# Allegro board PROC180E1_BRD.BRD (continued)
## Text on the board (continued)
PAGE_OUTLINE: LAYOUT BY | REVIEWED BY | APPROVED BY | SIGNATURES | AMB | BR | ZA | 290424 | DATE | SCALE: | SIZE | D | NONE | TEXAS INSTRUMENTS | AM62D EVM  BOARD | SHEET 1 OF 15 | PROC180 | Rev | E1
DISPLAY_TOP: 16. | 17. | 1. | 11. | 12. | 13. | 14. | 15. | 8. | 10 | 2. | 3. | 4. | 6. | 7. | 5. | 9. | IMPEDANCE MISTRAL SHALL APPROVE THE MODIFIED WIDTHS AND SPACING. | FABRICATE PCB IN ACCORDANCE WITH IPC-6012D, CLASS 2; PER IPC-6011.  PCB SHALL BE MANUFACTURED USING  ITEQ IT 180A OR EQUIVALENT | TRACE WIDTH SHALL BE MEASURED ON THE SURFACE IN CONTACT WITH THE LAMINATE. | TEST REQUIREMENTS: | THIEVING IS ALLOWED ONLY IN THE PANEL FRAME, NOT IN THE CIRCUIT AREA. | TEAR DROPS SHALL BE ADDED ON VIA'S AND THROUGH HOLE PADS IN ALL INTERNAL AND OUTER LAYERS. | ENSURE UL REGISTERED E-FILE NUMBER SHALL BE PRINTED ON THE PCB SILKSCREEN. | VIA ON PAD SHALL BE RESIN FILLED AND CAP-PLATED. | ALL HOLES SHALL BE LOCATED WITHIN 0.15MM  DIAMETER OF TRUE POSITION. | LAYER TO LAYER REGISTRATION SHALL BE WITHIN 0.125MM. | CONDUCTOR WIDTH SHALL NOT BE LESS THAN 20% FROM ITS ORIGINAL DATA. INCASE FOR MATCHING | BOARD FINISHED SHALL BE ACCORDING TO IPC-6012D CLASS 2. | AUTOMATED OPTICAL INSPECTION OF ALL THE LAYERS IS REQUIRED. | FINISH: | ALL UNCONNECTED VIA'S SHALL BE SUPPRESSED IF REQUIRED. | FINISHED PCB THICKNESS SHALL BE 0.0427" +/-10%. | MATERIALS: | BOW AND TWIST SHALL NOT EXCEED MORE THAN 0.75% OF THE DESIGN LENGTH. | MARKING: | MIN TRACE WIDTH/SPACING ON BOARD IS 0.003"/0.00339". | IF THE SILK SCREEN FALLS ON SOLDERABLE AREAS. | THICKNESS SHALL BE 0.04-0.06 MICRONS OF SOLDERABLE IMMERSION GOLD SURFACE. | 100% NET LIST ELECTRICAL VERIFICATION USING MISTRAL SUPPLIED IPC-D-356 NET LIST FOR OPENS AND SHORTS. | LAMINATE AND PREPREG (B-STAGE) TO BE IN ACCORDANCE WITH IPC-4101/126. | (MIN.TG 170) | THAT ARE 0.08(0.003") PER SIDE SHALL BE REDUCED IF REQUIRED. | SURFACE AND VIA HOLES FINISH SHALL NOT BE LESS THAN 20UM [0.00079"], INCASE OF LASER | ALL HOLES SURROUNDED BY LAND <=0.010" SHALL BE COMPLIANCE TO IPC6012, CLASS 2. | COPPER FOIL TO BE IN ACCORDANCE WITH IPC-MF-150. UNLESS OTHERWISE SPECIFIED, | ALL EXPOSED CONDUCTIVE PATTERN AREAS NOT COVERED WITH SOLDER MASK OR OTHER PLATING SHALL BE ENIG, | ELECTROLESS NICKEL/IMMERSION GOLD, ELECTROLESS NICKEL SHALL BE 3-6 MICRONS, TYPICAL IMMERSION GOLD | APPLY LIQUID PHOTO IMAGEABLE SOLDER MASK PER IPC-SM-840, CLASS H, TO BOTH SIDES OF THE BOARD OVER BARE COPPER. | VIA HOLES SHALL BE RESIN FILLED AND COVERED WITH SOLDER MASK. ONLY SOLDER MASK IMAGES | ALL OTHER SOLDER MASK IMAGES SHALL NOT BE ENLARGED. DEFAULT COLOUR OF SOLDER MASK SHALL BE GREEN. | SILKSCREEN SHALL BE WHITE, PERMANENT, ORGANIC, NON-CONDUCTIVE INK. THERE SHALL BE | VIA'S, BLIND VIA'S SHALL NOT BE LESS THAN 12UM [0.00047"] AND BURIED VIA'S SHALL NOT BE LESS THAN 15UM [0.0006"]. | BOARD SHALL MEET THE REQUIREMENTS OF UL-796E WITH FLAMMABILITY RATING OF MINIMUM 94V-0. UL LOGO, | NO SILKSCREEN ON ANY SOLDERABLE COMPONENT PAD. CLIPPING OF SILK SCREEN SHALL BE ALLOWED | MANUFACTURER'S IDENTIFICATION AND DATE CODE LETTER SHALL BE RENDERED IN SILKSCREEN. | THE COPPER FOIL THICKNESS TOLERANCES SHALL BE AS PER IPC 6012B TABLE NO.3-7 AND 3-8. | FABRICATION NOTES:
DIMENSION: P/N AM62A LPDDR4 FAB REV 1 | LAYER 1
User.5: AM62A LPDDR4 FAB REV 1 | P/N AM62A LPDDR4 FAB REV 1 | LAYER 12
User.7: C26 | R33 | R15 | R13 | R16 | R14 | R32 | R29 | R26 | R23 | R20 | C25 | C24 | R19 | C17 | R17 | C22 | C23 | R18 | R2 | R4 | R1 | R3 | H3 | H4 | R31 | J40 | R30 | R28 | R27 | R25 | R24 | R22 | R21 | 8
User.10: SECONDARY-SIDE-SIG | 15 | PROC180E1 ASSEMBLY BOTTOM
User.11: CARD PUSH OUT | CARD PUSH LOCK | CARD PUSH IN | PROC180E1 ASSEMBLY TOP
User.12: ASSEMBLY_BOTTOM | BOTTOM ASSEMBLY OF PROC167A
User.13: 2 | 4 | 3 | 6 | 5 | 32 | 8 | 7 | 16 | 11 | 64 | 17 | FTDI_LED | 49 | 33 | 48 | 12 | 13 | 9 | 10 | 36 | 24 | 37 | 28 | 19 | 25 | 27 | A12 | 5V0_TYPEA | TP105 | VDDR_CORE | 5B | 2A | 20 | 5A | 2B | 47 | 14 | A2 | 65 | 97 | A4 | 39 | 79 | 41 | C234 | 1B | 40 | 42 | 80 | 128 | A1 | MCU_RESETz | B1 | VDD_CANUART | R399 | L10 | R400 | VBUS_TYPEC2 | R281 | R282 | R290 | R291 | PORz_OUT | RESETSTATz | 18 | MCU_PORz | A3 | 96 | C115 | C88 | R77 | C108 | C93 | C37 | TP106 | C119 | C195 | PMIC_PGOOD | R21 | TP21 | C70 | U1 | R65 | TP85 | R54 | U2 | R309 | J22 | Y6 | C253 | U66 | C103 | R194 | LD2 | R260 | R259 | C300 | TP35 | C287 | R12 | D3 | R357 | C291 | R181 | R256 | U45 | R328 | R390 | Q2 | TP65 | C1 | U71 | R55 | C315 | U10 | C33 | C28 | C9 | C69 | U37 | R64 | R66 | C194 | C328 | U61 | U57 | U54 | R318 | R303 | R333 | L1 | R361 | U12 | R91 | TP102 | C302 | R86 | R395 | J24 | C123 | C288 | TP1 | J5 | R284 | R330 | PMIC_LPM_SEL | Q4 | LD7 | VBUS_TYPEC1 | LD4 | TP57 | C327 | C83 | R397 | J9 | TP82 | FL3 | R279 | D7 | R1 | C44 | C41 | C220 | TP16 | R268 | R274 | R292 | R222 | C34 | R322 | R326 | TP107 | C261 | LD6 | C263 | C326 | C164 | R102 | C306 | C289 | U38 | U46 | C309 | U69 | C58 | U9 | R96 | C292 | R223 | U64 | C106 | R265 | U3 | TP48 | 3V3_SYS | C312 | R296 | C80 | R294 | C191 | C79 | C197 | R166 | U17 | R199 | C145 | R257 | C184 | R120 | U32 | C10 | C19 | L6 | R391 | R195 | R317 | L4 | U42 | R175 | C313 | LD9 | U56 | R81 | TP103 | LD10 | C165 | C193 | U70 | R331 | C199 | C204 | R335 | TP46 | R216 | L7 | U72 | L5 | R164 | C39 | C94 | C228 | TP3 | C242 | C182 | C210 | TP81 | R210 | TP15 | U30 | R243 | TP4 | C254 | R401 | R398 | TP13 | TP7 | TP67 | C209 | C188 | R59 | R2 | C294 | C296 | TP47 | C144 | L8 | D6 | R234 | Y3 | R396 | C196 | R327 | R379 | R114 | R144 | TP56 | R288 | R115 | TP60 | MCU_WARM_RST | R253 | SW8 | R358 | TP69 | U31 | R375 | R252 | C159 | U47 | R198 | VPP_1V8 | U26 | J1 | SW6 | C247 | C251 | C156 | C284 | C299 | C286 | R304 | C297 | U74 | C290 | TP86 | TP88 | C316 | U8 | C11 | TP90 | C54 | C65 | C60 | R315 | R312 | R202 | R207 | R362 | TP31 | C100 | C124 | C237 | C114 | C238 | R339 | R143 | C95 | C118 | C120 | R373 | R376 | RA1 | C12 | R363 | R185 | C125 | U29 | C150 | C64 | L2 | C112 | U68 | R325 | J23 | TP34 | RA3 | C13 | R365 | R377 | R389 | R384 | U35 | C68 | C63 | D4 | Y2 | C14 | R46 | C77 | U20 | FL2 | R20 | RA4 | R165 | C173 | C154 | R142 | R336 | TP43 | R337 | C90 | C86 | OSPI_FLASH | C110 | C664 | VBAT_IN | U62 | A | C139 | R92 | RA2 | U28 | J7 | J2 | TP95 | R329 | L3 | C89 | C278 | C272 | U22 | C15 | R113 | R162 | C239 | R342 | R338 | C87 | C92 | C96 | U33 | U7 | C16 | R343 | J18 | R340 | U18 | R67 | R34 | R38 | TP41 | C17 | ACC* | C136 | C198 | R226 | C18 | R262 | R263 | R264 | R266 | R267 | R269 | R270 | R275 | TP44 | U23 | R121 | R161 | C274 | C279 | C32 | R90 | C38 | R84 | U14 | C178 | R112 | SW3 | R247 | R24 | C189 | U27 | U34 | C29 | TP61 | R277 | R285 | R283 | R238 | R242 | U5 | C187 | C177 | R278 | U51 | C236 | R225 | R124 | U43 | R107 | C235 | R280 | TP58 | U39 | C47 | C50 | C56 | U21 | C61 | R233 | C192 | C66 | R224 | R219 | R33 | J3 | TP64 | TP45 | TP94 | TP63 | TP2 | FL1 | R344 | J8 | U40 | C169 | C31 | C140 | C35 | C273 | C276 | TP33 | TP68 | R313 | R246 | TP51 | R306 | C243 | R346 | R25 | TP32 | C217 | C223 | C225 | R271 | TP19 | C46 | C73 | R235 | R227 | TP23 | R221 | R356 | U15 | R180 | U6 | J14 | R345 | R351 | R213 | J19 | TP20 | R32 | C104 | Q1 | R341 | R89 | R218 | TP38 | C67 | C62 | C48 | C57 | C51 | R85 | R83 | C105 | TP91 | J4 | Y1 | J13 | TP87 | R35 | TP89 | R27 | C250 | D1 | R58 | C271 | C277 | R28 | C267 | U60 | U11 | TP14 | LD5 | TP40 | TP77 | R56 | U41 | R69 | C99 | R289 | R295 | C170 | C171 | C167 | C172 | U16 | R18 | C168 | C174 | R385 | C160 | C175 | C161 | J12 | C176 | DGND | C4 | R57 | TP96 | R17 | R71 | R19 | C262 | R302 | C295 | R321 | U67 | U52 | C283 | R323 | FL4 | C285 | C230 | C280 | C270 | C282 | TP104 | C269 | R248 | R382 | C183 | C179 | R70 | SW5 | R272 | R386 | TP97 | R381 | U19 | R103 | SW4 | INT | RST | R196 | C310 | J15 | R404 | MOD1 | TP59 | TP75 | R293 | C102 | U73 | J16 | LD8 | C308 | R324 | C180 | R208 | R215 | C307 | R378 | C264 | D2 | Q3 | U50 | R308 | D5 | C7 | R250 | C321 | C59 | J11 | R53 | R93 | R88 | C248 | R305 | C8 | C107 | C324 | TP50 | TP55 | R286 | R39 | R258 | TP73 | C40 | C319 | R240 | C281 | TP80 | TP72 | C226 | C256 | C320 | C275 | C249 | R403 | C91 | C227 | R11 | C303 | R255 | C325 | C257 | R334 | C305 | TP76 | J25 | R16 | TP74 | FL5 | C322 | R374 | R402 | C207 | C323 | C301 | TP28 | C185 | R387 | D8 | R13 | R388 | R204 | D9 | TP52 | TP29 | C214 | R15 | R368 | J21 | C298 | Y4 | R251 | R369 | R200 | C113 | R380 | R72 | C216 | C213 | R170 | PMIC_CORE_CONFIG | R370 | R14 | C181 | TP30 | C211 | R261 | C219 | C162 | R82 | TP10 | R392 | C252 | R245 | C212 | R371 | TP54 | R40 | R49 | R79 | R244 | C5 | C258 | C311 | C218 | TP108 | R41 | R50 | U36 | C36 | R42 | C259 | R51 | C229 | U24 | R43 | R52 | C246 | C201 | U13 | R171 | R44 | R47 | C6 | C260 | C143 | C314 | C157 | R186 | R45 | R48 | SW7 | C317 | R172 | R316 | TP24 | C318 | R187 | R299 | R310 | C200 | R173 | TP79 | J20 | C224 | R300 | R311 | R188 | J6 | R116 | R174 | R383 | TP70 | C205 | R319 | U59 | R189 | R320 | FL9 | C255 | R182 | TP26 | R167 | R249 | R273 | R254 | R183 | R168 | R184 | TP27 | R169 | C163 | TP101 | R3 | TP83 | TP25 | R364 | C146 | R359 | R4 | R393 | C268 | R117 | FL10 | R367 | R372 | R349 | L9 | R348 | R394 | TP42 | R104 | R205 | R105 | R60 | TP99 | R61 | C53 | U65 | R62 | R87 | TP100 | R350 | R206 | C78 | R360 | TP98 | R125 | C52 | R63 | C151 | R197 | R332 | R123 | C84 | R5 | C85 | R6 | C127 | R80 | R190 | C111 | C116 | R26 | C2 | R176 | C158 | C98 | R191 | C152 | C97 | R177 | C117 | R22 | R192 | R145 | R23 | R94 | R178 | C266 | R193 | R146 | C153 | C265 | R179 | R99 | R7 | C131 | R147 | TP5 | R100 | R8 | C132 | C49 | R148 | C155 | C149 | U58 | R101 | R126 | R109 | C55 | R149 | R201 | R127 | R110 | C122 | R128 | R111 | R98 | TP6 | TP8 | R150 | R353 | R129 | C166 | TP9 | C71 | C82 | R151 | SW1 | R130 | R239 | R209 | FL7 | C109 | R78 | R163 | C206 | C74 | C81 | R152 | R131 | BMODE 8-15 | R228 | R355 | R132 | R217 | R133 | TP53 | R214 | FL6 | TP93 | C202 | R9 | FL8 | J10 | R10 | R68 | C3 | C42 | TP12 | C45 | R122 | C75 | C72 | C22 | TP49 | TP17 | C24 | TP22 | C186 | TP18 | C25 | C148 | R31 | C23 | R37 | R220 | R29 | R211 | R212 | TP62 | C126 | R106 | U49 | R36 | R118 | TP66 | R108 | R119 | U48 | TP11 | C147 | C43 | Y5 | C76 | TP36 | TP37 | U25 | R134 | R153 | TP92 | R154 | R135 | BMODE 0-7 | R136 | R155 | C203 | C30 | C20 | R352 | SW2 | R137 | R156 | C241 | LD1 | C121 | C26 | R138 | R157 | R229 | R139 | R158 | R97 | U55 | R230 | C27 | R140 | R159 | R75 | R95 | R314 | R141 | R231 | R160 | R76 | R74 | R354 | TP39 | C21 | C244 | C231 | R73 | R232 | R203 | C232 | TP78 | C233 | R236 | C101 | C240 | R237 | TP71 | J17 | C128 | C141 | C129 | C142 | R287 | C130 | C133 | LD3 | C137 | C190 | C215 | C134 | C221 | C138 | R276 | C135 | R241 | C208 | C222 | U4 | U63 | U44 | UART | OPT_IN | VDD_MMC1_SD | VDDSHV_SDIO | VMAIN | 3V3_MAIN | MCAN_HDR | FTDI | DIR | PD_PGM | EXP_LED | 5V0 | MCU_RESETSTATz | DIT | PORz | DVDD_1V8 | LINE_IN_2 | LINE_IN_1 | ETH0_CONN | LINE_OUT_1 | JTAG_CTI | SOC_LED | LINE_OUT_2 | ETH1_CONN | JTAG | FT4232_VBUS | AEC1 | MCU_MCAN_HDR | CPLD2_JTAG | TYPE-C | PWR | DRP | VDD_LPDDR4 | TYPE-A CONN | LPDDR4 | VDD_CORE | CPLD1_JTAG | eMMC | 3V3_XDS | VDD_2V5 | 110 | XDS | AEC2 | XDS_USB_VBUS | AM62D EVM | PROC180E1 | OPN# | AUDIO-AM62D-EVM | SL#
User.14: CARD PUSH OUT | CARD PUSH LOCK | CARD PUSH IN | 19 | 5 | 6 | 4 | 7 | 12 | 8 | 9 | 16 | 13 | 3 | 28 | 15 | 56 | 11 | 48 | 37 | 36 | 2 | 1 | A | B | 23 | 14 | 24 | 17 | 25 | 22 | 20 | 21 | 29 | 43 | C632 | R661 | C628 | R668 | C635 | C626 | C339 | C636 | R464 | R465 | uSD | U131 | R671 | FL18 | Q11 | R636 | C619 | D10 | R609 | R559 | C489 | R532 | C425 | C538 | D11 | C606 | C617 | C621 | U125 | Q6 | Q7 | C618 | U126 | C655 | U117 | C525 | U113 | D17 | R643 | R667 | U129 | R611 | R590 | R591 | C496 | R593 | R550 | C499 | R603 | C471 | R598 | R592 | 10 | C438 | C657 | C666 | C662 | C426 | R679 | C546 | C644 | C593 | C604 | C465 | C477 | C572 | C380 | C490 | C462 | C534 | C437 | C429 | U91 | C565 | C428 | C547 | C652 | C649 | C447 | C466 | C480 | C603 | R440 | U124 | R627 | C376 | R647 | C592 | R417 | C650 | R505 | R666 | C486 | R633 | C640 | C495 | R427 | C653 | R442 | C467 | C479 | R680 | Q5 | U132 | R587 | U92 | R434 | C630 | R619 | Q9 | C623 | R577 | FL15 | C448 | R567 | R441 | R597 | C505 | R553 | R596 | R560 | C646 | D13 | C613 | U78 | R543 | C422 | Q8 | R469 | R471 | R473 | R467 | R428 | C375 | FL14 | C559 | C645 | C402 | U85 | R514 | R508 | R683 | R608 | D14 | R503 | C622 | U118 | U130 | U119 | D12 | C510 | C526 | R574 | R484 | R538 | R542 | R615 | C512 | C609 | C481 | C579 | C590 | C584 | R496 | R563 | R573 | C544 | R642 | C531 | R472 | C410 | R468 | R626 | R466 | C557 | R630 | C578 | C585 | U89 | C594 | C591 | R463 | C407 | C411 | C404 | C405 | C570 | R462 | R474 | R504 | C551 | C540 | R449 | R452 | C558 | C566 | C582 | R475 | R486 | R431 | C388 | R433 | C390 | C583 | C562 | C548 | U84 | C378 | C564 | R454 | C543 | C389 | C571 | C530 | R453 | RA7 | U75 | C581 | C588 | R413 | C552 | C399 | R537 | C412 | C563 | R451 | R447 | R414 | R518 | R527 | R528 | R530 | C403 | C379 | R637 | R640 | R541 | R438 | R509 | C487 | C497 | FL13 | C431 | R529 | C423 | C616 | C614 | C442 | C395 | C527 | C521 | C514 | R623 | C620 | C394 | C520 | C421 | R461 | TP113 | R575 | TP116 | R456 | C370 | C367 | R429 | C360 | C365 | C362 | TP115 | R561 | R524 | R507 | R513 | R565 | C391 | TP112 | C352 | R437 | U82 | U86 | C414 | R512 | R517 | R525 | R605 | R602 | R457 | C415 | C372 | U87 | C409 | C350 | R510 | R515 | R519 | R536 | C455 | R487 | R421 | U120 | C354 | R624 | R607 | R549 | R601 | R511 | R516 | U88 | R526 | R576 | R606 | TP109 | C420 | R604 | C417 | C408 | R544 | C488 | C416 | R534 | RA5 | C511 | C384 | C515 | C366 | C369 | C364 | C361 | R625 | R622 | R533 | R430 | C359 | TP111 | U97 | TP114 | C469 | C500 | U102 | R616 | U76 | R569 | C473 | R610 | R618 | C351 | C353 | C349 | U107 | R578 | U83 | U81 | C665 | C670 | C396 | C453 | C508 | C454 | C485 | C461 | C445 | C483 | C663 | C456 | C668 | C493 | C659 | C658 | C502 | C556 | C545 | C554 | C550 | R670 | C634 | C625 | R648 | R649 | TP117 | U128 | R635 | R650 | C627 | R631 | C607 | C624 | C608 | C629 | C648 | C612 | D15 | J26 | C599 | U98 | R663 | FL17 | R659 | R664 | R658 | L12 | C575 | U133 | R614 | C574 | R674 | R613 | C643 | R547 | C513 | C478 | R546 | C457 | R660 | C509 | R572 | C654 | C641 | R612 | R586 | R645 | R678 | R571 | C424 | R682 | U114 | C524 | C381 | R681 | R644 | C460 | C532 | C651 | C435 | C642 | R436 | C555 | R646 | C491 | C536 | R426 | R673 | R657 | C444 | U79 | R425 | R662 | R656 | C450 | C501 | Q10 | R665 | R655 | R424 | C631 | C432 | R654 | R540 | R677 | R669 | C440 | R653 | C533 | R672 | C494 | C439 | R652 | C561 | R539 | R676 | R651 | C452 | U123 | C601 | C639 | U122 | C535 | C576 | C446 | R599 | D16 | C427 | C451 | C441 | R600 | U116 | C537 | C476 | C436 | C560 | R617 | C633 | C600 | U121 | C647 | C638 | R585 | C598 | R675 | U115 | R568 | R581 | C597 | R545 | C656 | R584 | R570 | C398 | C449 | C517 | C401 | FL11 | R641 | R638 | C567 | R481 | C637 | C397 | FL16 | C568 | C413 | R628 | C553 | C338 | C400 | C363 | C392 | R488 | C337 | R506 | R639 | R455 | C336 | C368 | R448 | R629 | R595 | C335 | U80 | R435 | R415 | R432 | C573 | R416 | C418 | C589 | C549 | C587 | C340 | C569 | C541 | R477 | R594 | R412 | R478 | C542 | R446 | R411 | R450 | R479 | C596 | R460 | R445 | C330 | R459 | R410 | R444 | C595 | R409 | R458 | R443 | R620 | C577 | R621 | R495 | C586 | R548 | R502 | C334 | R557 | R494 | R501 | FL12 | R493 | C522 | C475 | R500 | C406 | C333 | R492 | R558 | R499 | R491 | C615 | C474 | R535 | R589 | R498 | R588 | C332 | R634 | R497 | C464 | R632 | C463 | U127 | C331 | C610 | R408 | R407 | C377 | C329 | L11 | R406 | C503 | R405 | C504 | C498 | R562 | R482 | C344 | C518 | C348 | C393 | U77 | R480 | C347 | U93 | C602 | C343 | R531 | U90 | C374 | R476 | R556 | C358 | R485 | C611 | R554 | C356 | R555 | C387 | C383 | C516 | C419 | C386 | C382 | R483 | R523 | R490 | U109 | R522 | R489 | RA6 | C470 | C385 | R521 | C528 | R520 | C519 | C523 | C342 | C430 | U110 | C346 | C529 | R582 | R564 | C345 | TP110 | R579 | R566 | C341 | R552 | R583 | R347 | C371 | R551 | C605 | R580 | C373 | C357 | R423 | C355 | R422 | R419 | R418 | R420 | C484 | C482 | C443 | C433 | C667 | C434 | C661 | C468 | C660 | C459 | C472 | C507 | C458 | C492 | C506 | C669 | C539 | C580 | FOR EVALUATION ONLY; | NOT FCC APPROVED FOR RESALE | ASSY#
User.17: R37 | R44 | C31 | U3 | R34 | C30 | C29 | C32 | Q4 | J2 | U2 | MP1 | MP2 | MP3 | R24 | R26 | R28 | R30 | R23 | R25 | R27 | R29 | R10 | R20 | R22 | R21 | R9 | R32 | R31 | R36 | R6 | R35 | C1 | R41 | R42 | R18 | R43 | C2 | R40 | R12 | R38 | C34 | R39 | C33 | R8 | U1
User.18: R15 | C7 | C18 | C16 | C10 | C23 | R1 | R2 | R3 | C26 | C25 | C14 | C13 | C19 | C20 | C27 | C12 | C15 | C22 | R4 | R5 | R14 | C6 | C21 | C8 | C17 | C9 | C4 | C5 | C11 | C24 | J1 | MP9 | MP7 | MP8 | R33 | C3 | C28 | C35 | R7 | Q1 | Q2 | Q3
User.45: B | c | D | A | N | E | G | K | H | F | P | M | FIGURE | SIZE | 8.0 | 30.0 | 34.0 | 40.0 | 44.0 | 46.0 | 60.0 | 66.0 | 78.0 | 32.0 | 48.0 | 68.0 | 108.0 | 126.0 | 48.0x22.0 | 62.0x24.0 | 68.0x34.0 | 82.0x24.0 | 118.0x28.0 | 158.0x78.0 | DRILL CHART: TOP to BOTTOM | ALL UNITS ARE IN MILS | TOLERANCE | +3.0/-3.0 | +3.0/-2.0 | +2.0/-2.0 | PLATED | NON-PLATED | QTY | 3916 | 1 | 3 | 4 | 15 | 22 | 2 | 24 | 28 | 9 | 8 | SL# | 01 | 02 | 03 | 04 | 16 | 10 | 14 | 05 | 11 | 12 | 06 | 13 | 07 | 08 | 09 | STRIPLINE | MICROSTRIP | EDGE COUPLED STRIPLINE | EDGE COUPLED MICROSTRIP | TYPE | L1, L8 | L1 | L3 | L5 | L7 | LAYER | 5 | 6 | 5.25 | 11.3 | 15.4 | 10.3 | 6.7 | 7.5 | 4.7 | 4.8 | 3.5 | TRACEWIDTH(Mils) | NA | 4.6 | 7 | 5.7 | 5.8 | 6.5 | SPACING(Mils) | 50 | 40 | 80 | 90 | 120 | 133 | 33 | 66 | IMPEDANCE(Ohms) | REF LAYER | L2/L4 | L4/L6 | L6/L8 | L2, L7 | L4 | INNER-SIGNAL-2 | POWER-PLANE-2 | IMPEDANCE SPECIFICATIONS | PROC135E1 ASSEMBLY TOP (Variant 1) | PROC135E1 ASSEMBLY BOTTOM (Variant 1) | 6 - Provide serial numbers to the assembled boards for identification. | 7 - The assembled board are wrapped in ESD Covers(individual) and packed securely before shipment. | ASSEMBLY NOTES:- | 1 - All MSL components should be baked as per JEDEC standard. | 2 - PCB should be baked at 120 degree for 8 hours. | 3 - Board assembly must comply with workmanship standards IPC-A-610 Class 2, unless otherwise specified. | 4 - These assemblies are ESD sensitive, ESD precautions shall be observed. | 5 - These assemblies must be clean and free from flux and all contaminants. Use of no clean flux is not acceptable. | PROC101 E2 ASSEMBLY TOP | PROC101 E2 ASSEMBLY BOTTOM
